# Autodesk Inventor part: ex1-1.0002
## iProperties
Shininess: 64.0
Length Units: 11272
Angle Units: 11279
Time Units: 11290
Mass Units: 11286
Length Display Precision: 3
Angle Display Precision: 2
Compacted: True
Part Number: ex1-1.0002
Document SubType Name: Modeling
Created: 2003-11
Designer: Elise Moss
Cost Center: 0.4 lbmass
Authority: 11.8 in^3
Manufacturer: Standard
Standards Organization: Custom
Density: 0.0
Volumn: 0.0
Area: 0.0
PropertySet Name: Model Information
Control State: 0
Master: False
Checked Out: False
SaveDate: 2003-11-12
SaveTime: 16:21
TotalMass: 0.4 lbmass
TotalVolume: 11.8 in^3
Author: Elise Moss
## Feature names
1. Extrusion1
